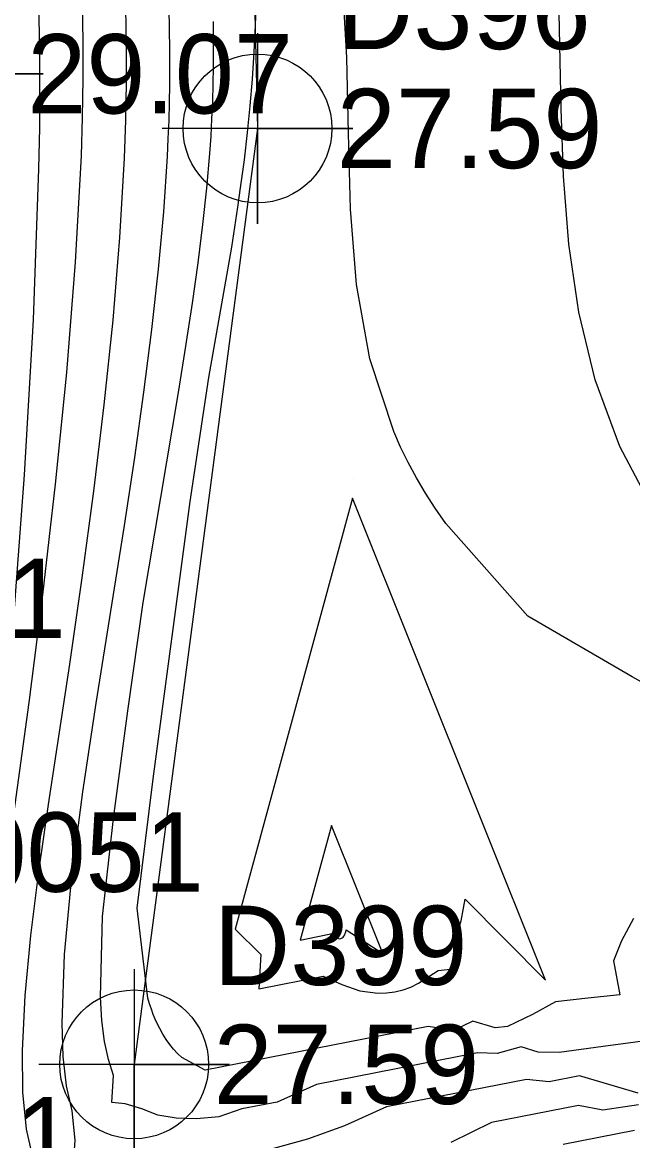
# Model space of a CAD drawing. Extents: x 2356077 to 2359823, y 225951 to 227822.
# Drawn here: x 2356596.02 to 2356615.24, y 227161.27 to 227196.5 of the extents above; entities that cross this region are included whole.
import ezdxf

# ---------------------------------------------------------------- set-up
doc = ezdxf.new("R2010")
doc.units = 0
for name, color, linetype in [('DTM Contours Major', 7, 'Continuous'), ('DTM Contours Minor', 7, 'Continuous'), ('Exist DTM Breakline', 7, 'Continuous'), ('Exist DTM Breakline Cogo Comment', 7, 'Continuous'), ('Exist DTM Breakline Cogo Elevation', 7, 'Continuous'), ('Exist DTM Breakline Cogo Number', 7, 'Continuous'), ('Exist DTM Breakline Cogo Point CELL', 7, 'Continuous'), ('PH Exist DTM Point', 7, 'Continuous')]:
    doc.layers.add(name, color=color, linetype=linetype)

msp = doc.modelspace()

# ---------------------------------------------------------------- linework, layer by layer
at = {"layer": 'DTM Contours Major'}
for points in [[(2356597.61, 227160.241), (2356597.681, 227161.281), (2356597.595, 227162.203), (2356597.414, 227162.996), (2356597.309, 227163.919), (2356597.272, 227164.966), (2356597.352, 227167.129), (2356597.585, 227169.588), (2356597.931, 227172.256), (2356598.348, 227175.046), (2356599.238, 227180.642), (2356599.563, 227182.79), (2356599.852, 227184.85), (2356600.103, 227186.826), (2356600.312, 227188.719), (2356600.476, 227190.533), (2356600.592, 227192.272), (2356600.619, 227192.843), (2356600.641, 227193.408), (2356600.657, 227193.969), (2356600.667, 227194.527), (2356600.672, 227195.085), (2356600.672, 227195.646), (2356600.65, 227196.936)], [(2356615.412, 227162.757), (2356613.57, 227163.308), (2356612.614, 227163.121), (2356611.896, 227163.194), (2356607.491, 227162.33), (2356606.173, 227161.73), (2356605.005, 227161.307), (2356603.746, 227160.968)]]:
    msp.add_lwpolyline(points, dxfattribs=at)
at = {"layer": 'DTM Contours Minor'}
for points in [[(2356615.934, 227181.068), (2356614.844, 227183.13), (2356614.067, 227185.234), (2356613.549, 227187.367), (2356613.233, 227189.511), (2356613.065, 227191.651), (2356612.989, 227193.773), (2356612.922, 227197.303), (2356612.86, 227199.058), (2356612.744, 227200.82), (2356612.545, 227202.601), (2356612.237, 227204.41), (2356611.544, 227207.191), (2356610.645, 227210.038), (2356608.63, 227215.835), (2356607.714, 227218.737), (2356606.993, 227221.611), (2356606.803, 227222.612), (2356606.65, 227223.61), (2356606.535, 227224.609), (2356606.456, 227225.612), (2356606.415, 227226.623)], [(2356595.734, 227177.462), (2356596.094, 227182.244), (2356596.378, 227187.13), (2356596.546, 227191.879), (2356596.568, 227193.177), (2356596.577, 227194.446), (2356596.573, 227195.69), (2356596.503, 227198.877)], [(2356594.816, 227160.192), (2356594.733, 227161.652), (2356594.769, 227163.246), (2356594.858, 227164.53), (2356594.99, 227165.871), (2356595.156, 227167.271), (2356595.351, 227168.733), (2356595.791, 227171.853), (2356596.232, 227175.067), (2356596.666, 227178.457), (2356597.071, 227181.95), (2356597.424, 227185.469), (2356597.701, 227188.94), (2356597.881, 227192.289), (2356597.918, 227193.516), (2356597.939, 227194.72), (2356597.942, 227195.909), (2356597.898, 227198.25)], [(2356596.384, 227160.607), (2356596.155, 227161.622), (2356596.041, 227162.793), (2356596.024, 227164.1), (2356596.109, 227165.84), (2356596.287, 227167.729), (2356596.539, 227169.74), (2356596.841, 227171.852), (2356597.516, 227176.28), (2356597.91, 227178.999), (2356598.276, 227181.732), (2356598.602, 227184.448), (2356598.878, 227187.12), (2356599.094, 227189.719), (2356599.238, 227192.216), (2356599.281, 227193.418), (2356599.303, 227194.598), (2356599.306, 227195.766), (2356599.272, 227197.547)], [(2356623.358, 227171.361), (2356615.232, 227175.876), (2356611.939, 227177.787), (2356609.359, 227180.712), (2356609.027, 227181.189), (2356608.72, 227181.668), (2356608.436, 227182.148), (2356608.174, 227182.631), (2356607.935, 227183.116), (2356607.717, 227183.604), (2356606.962, 227185.895), (2356606.545, 227188.236), (2356606.359, 227190.61), (2356606.294, 227193.002), (2356606.244, 227195.395), (2356606.101, 227197.775)], [(2356615.267, 227168.266), (2356614.896, 227167.558), (2356614.635, 227166.93), (2356614.844, 227165.855), (2356613.828, 227165.754), (2356612.811, 227165.644), (2356612.089, 227165.239), (2356611.298, 227164.861), (2356610.915, 227164.823), (2356610.212, 227165.033), (2356609.602, 227164.74), (2356609.2, 227164.799), (2356608.799, 227164.865), (2356601.785, 227163.489), (2356601.046, 227163.89), (2356600.913, 227164.016), (2356600.786, 227164.152), (2356600.666, 227164.298), (2356600.553, 227164.454), (2356600.447, 227164.62), (2356600.348, 227164.797), (2356600.276, 227164.94), (2356600.209, 227165.089), (2356600.146, 227165.245), (2356600.086, 227165.407), (2356600.031, 227165.575), (2356599.979, 227165.75), (2356599.637, 227168.587), (2356600.146, 227172.665), (2356601.305, 227181.401), (2356601.897, 227185.312), (2356602.615, 227189.419), (2356602.81, 227190.679), (2356602.897, 227191.286), (2356603.014, 227192.167), (2356603.114, 227193.026), (2356603.199, 227193.872), (2356603.27, 227194.712), (2356603.327, 227195.556), (2356603.369, 227196.41), (2356603.398, 227197.255)], [(2356617.531, 227164.661), (2356614.319, 227164.234), (2356612.933, 227164.043), (2356612.267, 227164.058), (2356611.732, 227164.218), (2356610.975, 227164.015), (2356610.352, 227164.031), (2356605.285, 227163.037), (2356604.048, 227162.483), (2356602.936, 227162.269), (2356602.214, 227162.013), (2356601.507, 227161.957), (2356600.863, 227161.97), (2356600.289, 227162.066), (2356599.79, 227162.265), (2356599.258, 227162.429), (2356598.837, 227162.469), (2356598.895, 227163.318), (2356598.731, 227163.818), (2356598.608, 227164.391), (2356598.525, 227165.046), (2356598.481, 227165.783), (2356598.543, 227168.331), (2356598.89, 227171.411), (2356599.341, 227174.812), (2356599.831, 227178.222), (2356600.938, 227184.838), (2356601.171, 227186.291), (2356601.378, 227187.649), (2356601.556, 227188.923), (2356601.707, 227190.126), (2356601.831, 227191.27), (2356601.926, 227192.366), (2356601.964, 227192.917), (2356601.994, 227193.462), (2356602.018, 227194.005), (2356602.034, 227194.55), (2356602.044, 227195.099), (2356602.047, 227195.656), (2356602.04, 227196.527)], [(2356606.424, 227181.505), (2356602.721, 227167.929), (2356603.534, 227167.128), (2356603.472, 227166.053), (2356605.494, 227166.449), (2356606.085, 227166.19), (2356606.648, 227165.99), (2356607.222, 227165.912), (2356607.49, 227165.918), (2356607.754, 227165.951), (2356608.011, 227166.013), (2356608.261, 227166.104), (2356608.501, 227166.225), (2356609.123, 227166.631), (2356609.68, 227166.687), (2356609.657, 227167.592), (2356609.841, 227168.194), (2356609.97, 227168.87), (2356612.498, 227166.321), (2356606.424, 227181.505)], [(2356605.761, 227171.197), (2356604.776, 227167.585), (2356605.827, 227167.799), (2356605.846, 227167.748), (2356605.872, 227167.705), (2356605.904, 227167.671), (2356605.94, 227167.645), (2356605.979, 227167.631), (2356606.019, 227167.627), (2356606.057, 227167.634), (2356606.093, 227167.652), (2356606.126, 227167.68), (2356606.152, 227167.712), (2356606.174, 227167.751), (2356606.192, 227167.796), (2356606.206, 227167.847), (2356606.216, 227167.903), (2356607.377, 227167.157), (2356605.761, 227171.197)], [(2356615.425, 227162.392), (2356614.309, 227162.222), (2356613.533, 227162.376), (2356610.802, 227161.841), (2356609.518, 227161.208)], [(2356615.297, 227161.583), (2356613.054, 227161.143)]]:
    msp.add_lwpolyline(points, dxfattribs=at)
at = {"layer": 'Exist DTM Breakline'}
msp.add_lwpolyline([(2356602.695, 227224.983), (2356603.426, 227193.155), (2356599.546, 227163.669)], dxfattribs=at)
at = {"layer": 'Exist DTM Breakline Cogo Point CELL'}
for points in [[(2356593.678, 227197.877), (2356593.678, 227191.877), (2356593.678, 227194.877), (2356596.678, 227194.877), (2356590.678, 227194.877)], [(2356603.426, 227196.155), (2356603.426, 227190.155), (2356603.426, 227193.155), (2356606.426, 227193.155), (2356600.426, 227193.155)], [(2356599.546, 227166.669), (2356599.546, 227160.669), (2356599.546, 227163.669), (2356602.546, 227163.669), (2356596.546, 227163.669)]]:
    msp.add_lwpolyline(points, dxfattribs=at)
for centre in [(2356603.426, 227193.155), (2356599.546, 227163.669)]:
    msp.add_circle(centre, 2.344, dxfattribs=at)
at = {"layer": 'PH Exist DTM Point'}
for p, q in [((2356606.464, 227182.123), (2356606.464, 227182.123)), ((2356605.521, 227167.46), (2356605.521, 227167.46))]:
    msp.add_line(p, q, dxfattribs=at)

# ---------------------------------------------------------------- texts
at = {"layer": 'Exist DTM Breakline Cogo Comment'}
for s, p in [('EL*40051', (2356582.708, 227177.104)), ('BL*40051', (2356587.047, 227169.106))]:
    msp.add_text(s, height=2.5, dxfattribs=at).set_placement(p)
at = {"layer": 'Exist DTM Breakline Cogo Elevation'}
for s, p in [('29.07', (2356596.178, 227193.627)), ('27.59', (2356605.926, 227191.905)), ('27.59', (2356602.046, 227162.419))]:
    msp.add_text(s, height=2.5, dxfattribs=at).set_placement(p)
at = {"layer": 'Exist DTM Breakline Cogo Number'}
for s, p in [('D396', (2356605.926, 227195.655)), ('D399', (2356602.046, 227166.169)), ('D401', (2356589.676, 227160.139))]:
    msp.add_text(s, height=2.5, dxfattribs=at).set_placement(p)

doc.saveas('drawing.dxf')
